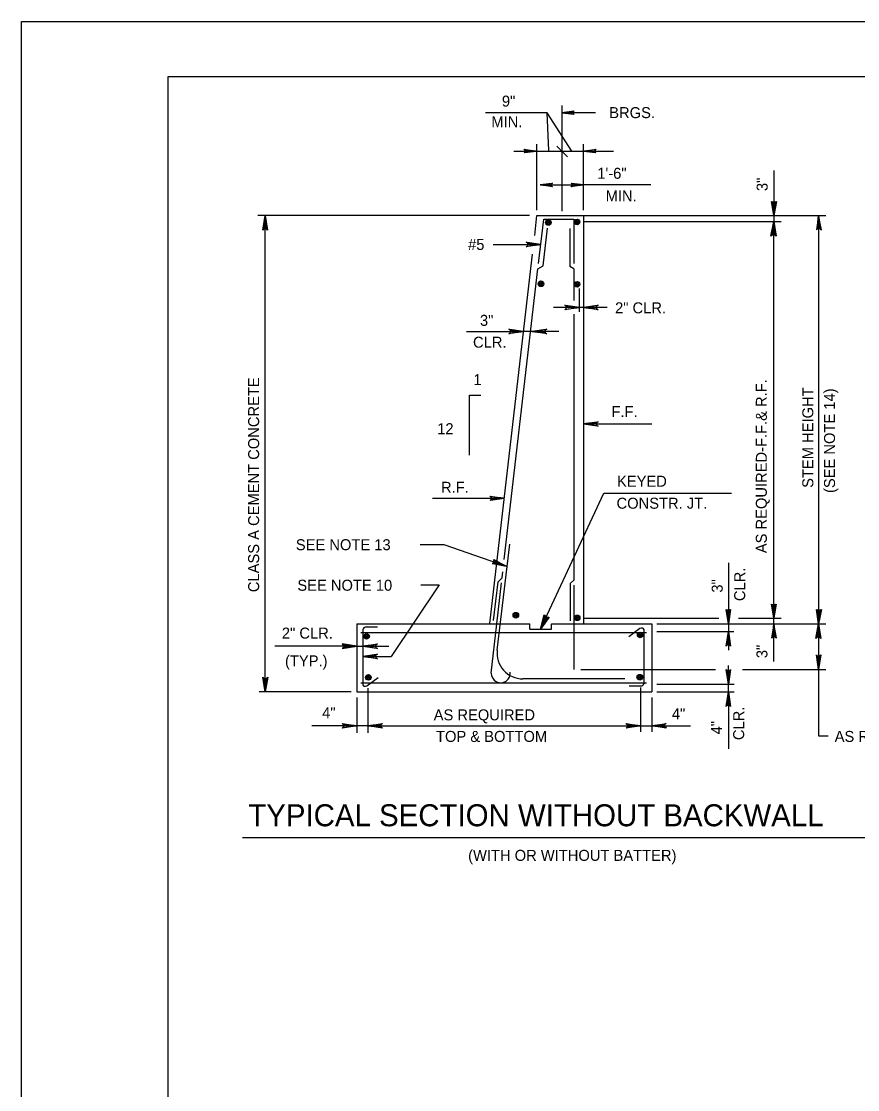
# Model space of a CAD drawing. Extents: x 235 to 2276, y 116 to 1308.
# Drawn here: x 579.4 to 807.5, y 1012.9 to 1304.4 of the extents above; entities that cross this region are included whole.
import ezdxf

# ---------------------------------------------------------------- set-up
doc = ezdxf.new("R2010")
doc.units = 0
doc.layers.add('1', color=7, linetype='Continuous')
doc.layers.add('PLT-BNDY', color=7, linetype='Continuous')

msp = doc.modelspace()

# ---------------------------------------------------------------- linework, layer by layer
at = {"layer": '1'}
for p, q in [((619.42, 725.41), (619.42, 1289.41)), ((619.42, 1289.41), (1405.42, 1289.41)), ((726.84, 1281.42), (726.84, 1252.65)), ((722.82, 1279.49), (705.99, 1279.49)), ((729.6, 1269.01), (722.82, 1279.49)), ((723.27, 1269.16), (722.82, 1279.49)), ((736.05, 1279.49), (726.84, 1279.49)), ((713.74, 1269.01), (740.98, 1269.01)), ((720.07, 1252.93), (720.07, 1270.93)), ((728.42, 1267.47), (725.49, 1270.4)), ((732.78, 1252.93), (732.78, 1270.93)), ((784.65, 1263.73), (784.65, 1249.8)), ((720.9, 1259.8), (732.78, 1259.8)), ((751.13, 1259.8), (732.78, 1259.8)), ((654.65, 1251.43), (643.9, 1251.43)), ((645.9, 1121.43), (645.9, 1251.43)), ((718.06, 1251.43), (654.65, 1251.43)), ((719.44, 1245.99), (720.07, 1251.43)), ((720.07, 1251.43), (732.78, 1251.43)), ((732.65, 1251.43), (798.9, 1251.43)), ((732.78, 1251.43), (732.78, 1140.05)), ((796.9, 1251.43), (796.9, 1140.05)), ((720.48, 1238.35), (721.97, 1250.43)), ((721.8, 1237.73), (722.95, 1247.96)), ((721.97, 1250.43), (730.15, 1250.43)), ((729.03, 1247.93), (729.03, 1237.55)), ((730.15, 1250.43), (730.15, 1238.3)), ((732.65, 1249.8), (786.65, 1249.8)), ((784.65, 1141.55), (784.65, 1249.8)), ((708.15, 1243.54), (721.12, 1243.54)), ((707.21, 1140.15), (718.86, 1240.91)), ((711.14, 1157.53), (720.3, 1236.92)), ((720.3, 1236.92), (721.8, 1237.73)), ((730.15, 1236.93), (729.03, 1237.55)), ((730.15, 1236.93), (730.15, 1228.28)), ((731.64, 1225.12), (731.64, 1231.51)), ((731.64, 1226.37), (724.57, 1226.37)), ((730.15, 1224.49), (730.15, 1151.93)), ((732.78, 1226.37), (731.64, 1226.37)), ((739.21, 1226.37), (732.78, 1226.37)), ((700.88, 1219.8), (716.42, 1219.8)), ((726.03, 1219.8), (716.42, 1219.8)), ((701.69, 1202.38), (704.73, 1202.38)), ((701.69, 1186), (701.69, 1202.38)), ((732.78, 1194.55), (751.4, 1194.55)), ((720.99, 1138.55), (738.28, 1175.68)), ((738.28, 1175.68), (773.15, 1175.68)), ((691.53, 1174.27), (711.15, 1174.27)), ((688.22, 1161.69), (694.67, 1161.69)), ((694.67, 1161.69), (711.71, 1155.71)), ((709.24, 1132.83), (712.64, 1161.72)), ((772.28, 1156.7), (772.28, 1140.05)), ((708.24, 1140.89), (709.47, 1151.5)), ((709.47, 1151.5), (710.57, 1152.6)), ((710.57, 1152.6), (710.76, 1154.24)), ((729.15, 1151.05), (730.15, 1151.93)), ((693.4, 1150.68), (680.27, 1131.11)), ((688.4, 1150.68), (693.4, 1150.68)), ((709.12, 1140.05), (710.41, 1151.2)), ((729.15, 1151.05), (729.15, 1140.8)), ((730.15, 1150.55), (730.15, 1127.55)), ((670.9, 1140.05), (670.9, 1121.43)), ((670.9, 1140.05), (718.15, 1140.05)), ((707.61, 1126.52), (709.12, 1140.05)), ((718.15, 1138.55), (718.15, 1140.05)), ((724.03, 1140.05), (751.4, 1140.05)), ((724.03, 1138.55), (724.03, 1140.05)), ((732.65, 1141.55), (769.65, 1141.55)), ((751.4, 1140.05), (751.4, 1121.43)), ((752.78, 1140.05), (798.9, 1140.05)), ((772.28, 1140.05), (772.28, 1132.8)), ((775.03, 1141.55), (786.65, 1141.55)), ((784.65, 1129.73), (784.65, 1141.55)), ((796.9, 1140.05), (796.9, 1127.55)), ((672.03, 1137.69), (749.94, 1137.69)), ((672.53, 1138.38), (672.53, 1123.48)), ((676.57, 1139.15), (673.57, 1139.15)), ((718.15, 1138.55), (724.03, 1138.55)), ((748.17, 1138.72), (745.17, 1136.47)), ((749.28, 1123.85), (749.28, 1138.38)), ((752.78, 1137.93), (773.78, 1137.93)), ((670.9, 1133.9), (648.55, 1133.9)), ((670.9, 1133.9), (679.62, 1133.9)), ((672.53, 1131.11), (680.27, 1131.11)), ((772.28, 1121.43), (772.28, 1128.68)), ((673.64, 1123.14), (676.76, 1125.39)), ((732.03, 1127.55), (768.74, 1127.55)), ((776.12, 1127.55), (798.9, 1127.55)), ((796.9, 1127.55), (796.9, 1109.43)), ((672.03, 1123.93), (749.94, 1123.93)), ((673.9, 1122.43), (673.9, 1110.3)), ((744, 1125.01), (716.19, 1125.01)), ((745.24, 1123.08), (748.24, 1123.08)), ((748.28, 1122.68), (748.28, 1110.55)), ((752.78, 1123.55), (773.9, 1123.55)), ((654.65, 1121.43), (644.28, 1121.43)), ((669.4, 1121.43), (654.65, 1121.43)), ((670.9, 1121.43), (751.4, 1121.43)), ((670.9, 1119.93), (670.9, 1110.3)), ((751.4, 1119.93), (751.4, 1110.55)), ((752.78, 1121.43), (773.9, 1121.43)), ((772.28, 1121.43), (772.28, 1105.88)), ((673.9, 1112.18), (658.65, 1112.18)), ((673.9, 1112.18), (742.03, 1112.18)), ((742.03, 1112.18), (748.28, 1112.18)), ((748.28, 1112.18), (761.92, 1112.18)), ((796.9, 1109.43), (799.53, 1109.43)), ((639.78, 1081.71), (831.9, 1081.71))]:
    msp.add_line(p, q, dxfattribs=at)
for points in [[(730.09, 1279.12), (729.96, 1279.37), (726.84, 1279.49), (730.09, 1279.12), (730.21, 1278.99), (726.84, 1279.49), (729.96, 1279.62), (730.09, 1279.87), (726.84, 1279.49), (730.21, 1279.99), (730.09, 1279.87)], [(716.7, 1269.39), (716.82, 1269.14), (719.95, 1269.01), (716.7, 1269.39), (716.57, 1269.51), (719.95, 1269.01), (716.82, 1268.89), (716.7, 1268.64), (719.95, 1269.01), (716.57, 1268.51), (716.7, 1268.64)], [(736.03, 1268.63), (735.9, 1268.88), (732.78, 1269.01), (736.03, 1268.63), (736.15, 1268.51), (732.78, 1269.01), (735.9, 1269.13), (736.03, 1269.38), (732.78, 1269.01), (736.15, 1269.51), (736.03, 1269.38)], [(724.15, 1259.43), (724.03, 1259.68), (720.9, 1259.8), (724.15, 1259.43), (724.28, 1259.3), (720.9, 1259.8), (724.03, 1259.93), (724.15, 1260.18), (720.9, 1259.8), (724.28, 1260.3), (724.15, 1260.18)], [(724.15, 1259.43), (724.03, 1259.68), (720.9, 1259.8), (724.15, 1259.43), (724.28, 1259.3), (720.9, 1259.8), (724.03, 1259.93), (724.15, 1260.18), (720.9, 1259.8), (724.28, 1260.3), (724.15, 1260.18)], [(729.53, 1260.18), (729.65, 1259.93), (732.78, 1259.8), (729.53, 1260.18), (729.4, 1260.3), (732.78, 1259.8), (729.65, 1259.68), (729.53, 1259.43), (732.78, 1259.8), (729.4, 1259.3), (729.53, 1259.43)], [(785.15, 1255.18), (784.9, 1255.05), (784.65, 1251.43), (785.15, 1255.18), (785.4, 1255.3), (784.65, 1251.43), (784.53, 1255.05), (784.28, 1255.18), (784.65, 1251.43), (784.03, 1255.3), (784.28, 1255.18)], [(645.53, 1247.68), (645.78, 1247.8), (645.9, 1251.43), (645.53, 1247.68), (645.28, 1247.43), (645.9, 1251.43), (646.15, 1247.8), (646.4, 1247.68), (645.9, 1251.43), (646.53, 1247.43), (646.4, 1247.68)], [(797.4, 1247.68), (797.15, 1247.8), (796.9, 1251.43), (797.4, 1247.68), (797.65, 1247.55), (796.9, 1251.43), (796.78, 1247.8), (796.53, 1247.68), (796.9, 1251.43), (796.28, 1247.55), (796.53, 1247.68)], [(784.15, 1246.05), (784.4, 1246.18), (784.65, 1249.8), (784.15, 1246.05), (783.9, 1245.8), (784.65, 1249.8), (784.78, 1246.18), (785.03, 1246.05), (784.65, 1249.8), (785.28, 1245.8), (785.03, 1246.05)], [(717.37, 1244.04), (717.5, 1243.79), (721.12, 1243.54), (717.37, 1244.04), (717.12, 1244.16), (721.12, 1243.54), (717.5, 1243.41), (717.37, 1243.04), (721.12, 1243.54), (717.12, 1242.91), (717.37, 1243.04)], [(727.89, 1226.87), (728.02, 1226.62), (731.64, 1226.37), (727.89, 1226.87), (727.64, 1226.99), (731.64, 1226.37), (728.02, 1226.24), (727.89, 1225.87), (731.64, 1226.37), (727.64, 1225.74), (727.89, 1225.87)], [(736.53, 1225.87), (736.4, 1226.12), (732.78, 1226.37), (736.53, 1225.87), (736.78, 1225.74), (732.78, 1226.37), (736.4, 1226.49), (736.53, 1226.87), (732.78, 1226.37), (736.78, 1226.99), (736.53, 1226.87)], [(712.67, 1220.3), (712.79, 1220.05), (716.42, 1219.8), (712.67, 1220.3), (712.42, 1220.43), (716.42, 1219.8), (712.79, 1219.68), (712.67, 1219.3), (716.42, 1219.8), (712.42, 1219.18), (712.67, 1219.3)], [(722.53, 1219.3), (722.4, 1219.55), (718.78, 1219.8), (722.53, 1219.3), (722.78, 1219.18), (718.78, 1219.8), (722.4, 1219.93), (722.53, 1220.3), (718.78, 1219.8), (722.78, 1220.43), (722.53, 1220.3)], [(736.53, 1194.05), (736.4, 1194.43), (732.78, 1194.55), (736.53, 1194.05), (736.78, 1193.93), (732.78, 1194.55), (736.4, 1194.8), (736.53, 1195.05), (732.78, 1194.55), (736.78, 1195.18), (736.53, 1195.05)], [(707.4, 1174.65), (707.53, 1174.4), (711.15, 1174.27), (707.4, 1174.65), (707.28, 1174.9), (711.15, 1174.27), (707.53, 1174.02), (707.4, 1173.77), (711.15, 1174.27), (707.28, 1173.65), (707.4, 1173.77)], [(708.31, 1157.34), (708.35, 1157.06), (711.71, 1155.71), (708.31, 1157.34), (708.28, 1157.61), (711.71, 1155.71), (708.22, 1156.71), (708.02, 1156.51), (711.71, 1155.71), (707.86, 1156.44), (708.02, 1156.51)], [(772.78, 1143.8), (772.53, 1143.68), (772.28, 1140.05), (772.78, 1143.8), (772.9, 1143.93), (772.28, 1140.05), (772.15, 1143.68), (771.9, 1143.8), (772.28, 1140.05), (771.65, 1143.93), (771.9, 1143.8)], [(785.03, 1145.3), (784.78, 1145.18), (784.65, 1141.55), (785.03, 1145.3), (785.28, 1145.43), (784.65, 1141.55), (784.4, 1145.18), (784.15, 1145.3), (784.65, 1141.55), (784.03, 1145.43), (784.15, 1145.3)], [(797.4, 1143.8), (797.15, 1143.68), (796.9, 1140.05), (797.4, 1143.8), (797.65, 1143.93), (796.9, 1140.05), (796.78, 1143.68), (796.53, 1143.8), (796.9, 1140.05), (796.28, 1143.93), (796.53, 1143.8)], [(722.97, 1141.77), (722.72, 1141.76), (720.99, 1138.55), (722.97, 1141.77), (723.21, 1141.91), (720.99, 1138.55), (722.33, 1141.99), (722.2, 1142.11), (720.99, 1138.55), (722.06, 1142.48), (722.2, 1142.11)], [(723.11, 1141.68), (722.86, 1141.68), (720.99, 1138.55), (723.11, 1141.68), (723.36, 1141.8), (720.99, 1138.55), (722.49, 1141.93), (722.36, 1142.05), (720.99, 1138.55), (722.24, 1142.43), (722.36, 1142.05)], [(785.15, 1136.3), (784.9, 1136.43), (784.65, 1140.05), (785.15, 1136.3), (785.4, 1136.18), (784.65, 1140.05), (784.53, 1136.43), (784.28, 1136.3), (784.65, 1140.05), (784.03, 1136.18), (784.28, 1136.3)], [(796.4, 1136.3), (796.65, 1136.43), (796.9, 1140.05), (796.4, 1136.3), (796.15, 1136.05), (796.9, 1140.05), (797.03, 1136.43), (797.28, 1136.3), (796.9, 1140.05), (797.53, 1136.05), (797.28, 1136.3)], [(771.78, 1134.18), (772.15, 1134.3), (772.28, 1137.93), (771.78, 1134.18), (771.65, 1133.93), (772.28, 1137.93), (772.53, 1134.3), (772.78, 1134.18), (772.28, 1137.93), (772.9, 1133.93), (772.78, 1134.18)], [(667.15, 1133.4), (667.28, 1133.77), (670.9, 1133.9), (667.15, 1133.4), (666.9, 1133.27), (670.9, 1133.9), (667.28, 1134.15), (667.15, 1134.4), (670.9, 1133.9), (666.9, 1134.52), (667.15, 1134.4)], [(676.28, 1133.4), (676.15, 1133.77), (672.53, 1133.9), (676.28, 1133.4), (676.53, 1133.27), (672.53, 1133.9), (676.15, 1134.15), (676.28, 1134.4), (672.53, 1133.9), (676.53, 1134.52), (676.28, 1134.4)], [(676.28, 1130.61), (676.15, 1130.99), (672.53, 1131.11), (676.28, 1130.61), (676.53, 1130.49), (672.53, 1131.11), (676.15, 1131.36), (676.28, 1131.61), (672.53, 1131.11), (676.53, 1131.74), (676.28, 1131.61)], [(797.28, 1131.3), (797.03, 1131.18), (796.9, 1127.55), (797.28, 1131.3), (797.53, 1131.55), (796.9, 1127.55), (796.65, 1131.18), (796.4, 1131.3), (796.9, 1127.55), (796.28, 1131.55), (796.4, 1131.3)], [(646.4, 1125.18), (646.15, 1125.05), (645.9, 1121.43), (646.4, 1125.18), (646.65, 1125.43), (645.9, 1121.43), (645.78, 1125.05), (645.53, 1125.18), (645.9, 1121.43), (645.28, 1125.43), (645.53, 1125.18)], [(772.78, 1127.3), (772.53, 1127.18), (772.28, 1123.55), (772.78, 1127.3), (772.9, 1127.55), (772.28, 1123.55), (772.15, 1127.18), (771.9, 1127.3), (772.28, 1123.55), (771.65, 1127.55), (771.9, 1127.3)], [(771.78, 1117.68), (772.15, 1117.8), (772.28, 1121.43), (771.78, 1117.68), (771.65, 1117.43), (772.28, 1121.43), (772.53, 1117.8), (772.78, 1117.68), (772.28, 1121.43), (772.9, 1117.43), (772.78, 1117.68)], [(667.15, 1112.68), (667.28, 1112.43), (670.9, 1112.18), (667.15, 1112.68), (667.03, 1112.8), (670.9, 1112.18), (667.28, 1112.05), (667.15, 1111.8), (670.9, 1112.18), (667.03, 1111.55), (667.15, 1111.8)], [(677.65, 1111.8), (677.53, 1112.05), (673.9, 1112.18), (677.65, 1111.8), (677.9, 1111.55), (673.9, 1112.18), (677.53, 1112.43), (677.65, 1112.68), (673.9, 1112.18), (677.9, 1112.8), (677.65, 1112.68)], [(744.53, 1112.68), (744.78, 1112.43), (748.28, 1112.18), (744.53, 1112.68), (744.4, 1112.8), (748.28, 1112.18), (744.78, 1112.05), (744.65, 1111.8), (748.28, 1112.18), (744.4, 1111.55), (744.65, 1111.8)], [(755.15, 1111.8), (754.9, 1112.05), (751.4, 1112.18), (755.15, 1111.8), (755.28, 1111.55), (751.4, 1112.18), (754.9, 1112.43), (755.03, 1112.68), (751.4, 1112.18), (755.28, 1112.8), (755.03, 1112.68)]]:
    msp.add_lwpolyline(points, dxfattribs=at)
for centre, radius in [((723.18, 1249.54), 0.763), ((723.18, 1249.54), 0.545), ((723.18, 1249.54), 0.298), ((723.18, 1249.54), 0.15), ((723.18, 1249.54), 0.0644), ((730.99, 1249.69), 0.763), ((730.99, 1249.69), 0.545), ((730.99, 1249.69), 0.298), ((730.99, 1249.69), 0.15), ((730.99, 1249.69), 0.0644), ((721.15, 1232.81), 0.763), ((721.15, 1232.81), 0.545), ((721.15, 1232.81), 0.298), ((730.99, 1232.67), 0.763), ((730.99, 1232.67), 0.545), ((721.15, 1232.81), 0.15), ((721.15, 1232.81), 0.0644), ((730.99, 1232.67), 0.298), ((730.99, 1232.67), 0.15), ((730.99, 1232.67), 0.0644), ((714.3, 1142.37), 0.763), ((714.3, 1142.37), 0.545), ((714.3, 1142.37), 0.298), ((714.3, 1142.37), 0.15), ((714.3, 1142.37), 0.0644), ((731.04, 1141.66), 0.763), ((731.04, 1141.66), 0.545), ((731.04, 1141.66), 0.298), ((731.04, 1141.66), 0.15), ((731.04, 1141.66), 0.0644), ((673.58, 1136.61), 0.763), ((673.58, 1136.61), 0.545), ((673.58, 1136.61), 0.298), ((748.23, 1136.99), 0.763), ((748.23, 1136.99), 0.545), ((748.23, 1136.99), 0.298), ((748.23, 1136.99), 0.15), ((748.23, 1136.99), 0.0644), ((673.58, 1136.61), 0.15), ((673.58, 1136.61), 0.0644), ((674.07, 1125.4), 0.763), ((674.07, 1125.4), 0.545), ((674.07, 1125.4), 0.298), ((674.07, 1125.4), 0.15), ((674.07, 1125.4), 0.0644), ((748.11, 1125.45), 0.763), ((748.11, 1125.45), 0.545), ((748.11, 1125.45), 0.298), ((748.11, 1125.45), 0.15), ((748.11, 1125.45), 0.0644)]:
    msp.add_circle(centre, radius, dxfattribs=at)
for centre, radius, start, end in [((716.19, 1132.01), 7, 173.2902, 270), ((710.19, 1126.52), 2.58, 180, 7.5933)]:
    msp.add_arc(centre, radius, start, end, dxfattribs=at)
for centre, major_axis, start_param, end_param in [((673.57, 1138.38), (-1.04, 0), 4.712389, 6.283185), ((748.63, 1138.38), (-0.65, 0), 3.141593, 5.497787), ((673.18, 1123.48), (0.65, 0), 3.141593, 5.497787), ((748.24, 1123.85), (1.04, 0), 4.712389, 6.283185)]:
    msp.add_ellipse(centre, major_axis=major_axis, ratio=0.739792, start_param=start_param, end_param=end_param, dxfattribs=at)
at = {"layer": 'PLT-BNDY'}
msp.add_lwpolyline([(579.42, 1304.41), (1420.42, 1304.41), (1420.42, 710.41), (579.42, 710.41)], close=True, dxfattribs=at)

# ---------------------------------------------------------------- texts
at = {"layer": '1'}
for s, height, p in [('9"', 3, (710.5, 1281.15)), ('  BRGS.', 3, (737.55, 1278.01)), ('MIN.', 3, (707.62, 1275.54)), ('1\'-6"', 3, (736.52, 1261.46)), ('MIN.', 3, (738.8, 1255.28)), ('#5', 3, (701.28, 1242.05)), ('2" CLR.', 3, (741.37, 1224.74)), ('3"', 3, (704.52, 1221.33)), ('CLR.', 3, (702.62, 1215.37)), ('1', 3, (702.74, 1205.15)), ('F.F.', 3, (740.4, 1196.43)), ('12', 3.003, (692.85, 1191.76)), ('R.F.', 3, (693.9, 1175.77)), ('KEYED', 3, (741.9, 1177.43)), ('CONSTR. JT.', 3, (741.78, 1171.43)), ('SEE NOTE 13', 3, (654.29, 1160.11)), ('SEE NOTE 10', 3, (654.71, 1149.05)), ('2" CLR.', 3, (650.48, 1135.99)), ('(TYP.)', 3, (651.34, 1128.42)), ('4"', 3, (661.47, 1114.24)), (' AS REQUIRED ', 3, (690.78, 1113.68)), ('4"', 3, (756.86, 1113.95)), ('TOP & BOTTOM', 3, (692.53, 1107.8)), ('AS REQUIRED', 3, (801.28, 1107.8)), ('TYPICAL SECTION WITHOUT BACKWALL', 6, (641.32, 1084.78)), ('(WITH OR WITHOUT BATTER)', 3, (701.29, 1075.34))]:
    msp.add_text(s, height=height, dxfattribs=at).set_placement(p)
for s, p in [('3"', (782.99, 1258.11)), (' CLASS A CEMENT CONCRETE ', (644.28, 1147.55)), (' AS REQUIRED-F.F.& R.F. ', (782.77, 1158.18)), ('STEM HEIGHT', (795.45, 1177.12)), ('(SEE NOTE 14)', (801.37, 1175.72)), ('CLR.', (776.87, 1146.22)), ('3"', (770.74, 1148.53)), ('3"', (782.94, 1130.65)), ('CLR.', (776.59, 1108.29)), ('4"', (770.55, 1109.85))]:
    msp.add_text(s, height=3, rotation=90, dxfattribs=at).set_placement(p)

doc.saveas('drawing.dxf')
